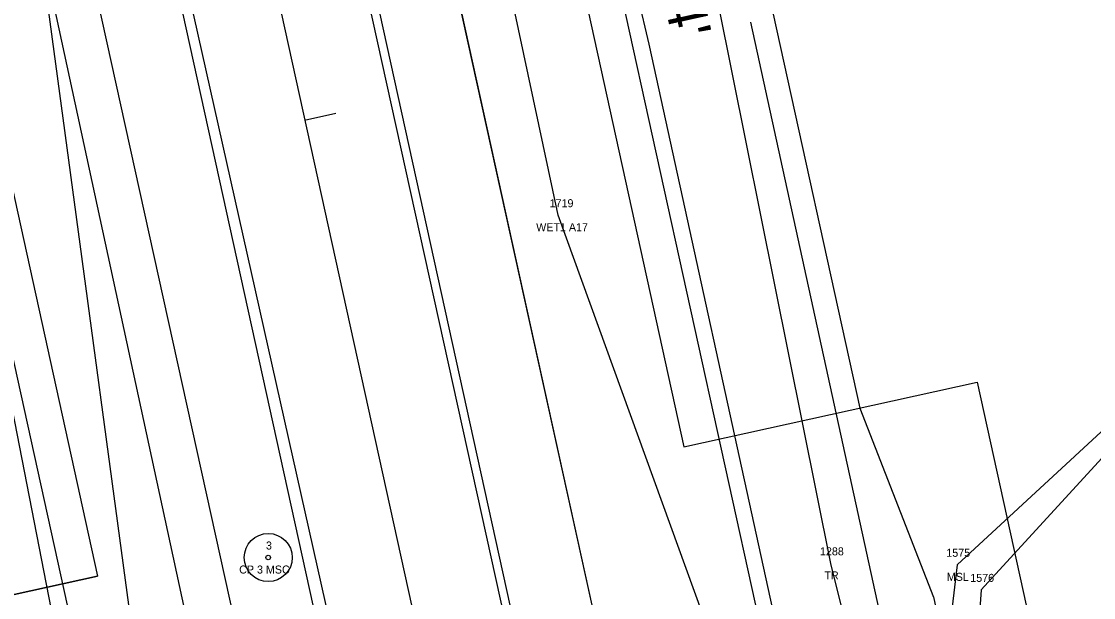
# Model space of a CAD drawing. Extents: x 2520975 to 2526538, y 881018 to 888064.
# Drawn here: x 2523710.8 to 2523844.7, y 885257.8 to 885329.7 of the extents above; entities that cross this region are included whole.
import ezdxf

# ---------------------------------------------------------------- set-up
doc = ezdxf.new("R2010")
doc.units = 0
for name, color, linetype in [('RD_EV_JurisArea', 7, 'Continuous'), ('RD_EX_DV_Prop', 7, 'Continuous'), ('RD_EX_H2O', 7, 'Continuous'), ('RD_EX_H2O_txCode', 7, 'Continuous'), ('RD_EX_H2O_WetLd_txCode', 7, 'Continuous'), ('RD_EX_Misc', 7, 'Continuous'), ('RD_EX_Misc_txCode', 7, 'Continuous'), ('RD_EX_Road', 7, 'Continuous'), ('RD_EX_RW', 7, 'Continuous'), ('RD_EX_VEG', 7, 'Continuous'), ('RD_EX_VEG_txCode', 7, 'Continuous'), ('RD_HC_Cl', 7, 'Continuous'), ('RD_HC_Data', 7, 'Continuous'), ('RD_HC_Data_Tic', 7, 'Continuous'), ('RD_HC_txCode', 7, 'Continuous'), ('RD_PD_BCA', 7, 'Continuous'), ('RD_PD_CstnLmt', 7, 'Continuous'), ('RD_PD_DR_ErosCtrl', 7, 'Continuous'), ('RD_PD_Final_TrvlWay', 7, 'Continuous'), ('RD_PD_GR', 7, 'Continuous'), ('RD_PD_RW', 7, 'Continuous'), ('RD_SMD_Locator', 7, 'Continuous')]:
    doc.layers.add(name, color=color, linetype=linetype)

msp = doc.modelspace()

# ---------------------------------------------------------------- linework, layer by layer
at = {"layer": 'RD_EV_JurisArea'}
for points in [[(2523761.17, 885134.03), (2523740.58, 885149.03), (2523730.55, 885209.77), (2523710.6, 885357.47), (2523698.09, 885411.19), (2523674.93, 885498.62), (2523657.6, 885564.24), (2523640.82, 885610.87), (2523583.66, 885726.91), (2523539.21, 885693.17), (2523494.42, 885646.98)], [(2523761.17, 885134.03), (2523808.21, 885149.21), (2523821.91, 885178.64), (2523802.85, 885236.55), (2523777.81, 885305.56), (2523748.2, 885444.32), (2523730.68, 885516.88), (2523708.64, 885617.3), (2523698.71, 885662.02), (2523727.83, 885665.82), (2523757.3, 885671.75)]]:
    msp.add_lwpolyline(points, dxfattribs=at)
at = {"layer": 'RD_EX_DV_Prop'}
for p, q in [((2523677.79, 885802.27), (2523793.53, 885276.66)), ((2523670.71, 885485.63), (2523720.28, 885260.53)), ((2523793.53, 885276.66), (2523830.15, 885284.72)), ((2523830.15, 885284.72), (2523894.67, 884991.74)), ((2523720.28, 885260.53), (2523683.66, 885252.46))]:
    msp.add_line(p, q, dxfattribs=at)
at = {"layer": 'RD_EX_H2O'}
msp.add_lwpolyline([(2524064.86, 885165.15), (2524036.37, 885213.78), (2524057.22, 885252.72), (2524031.95, 885291.63), (2523983.25, 885326.3), (2523940.61, 885311.83), (2523904.84, 885305.01), (2523874.98, 885272.1), (2523850.32, 885280.24), (2523830.66, 885258.8), (2523826.93, 885206.61)], dxfattribs=at)
at = {"layer": 'RD_EX_Misc'}
msp.add_lwpolyline([(2524066.31, 885165.35), (2524037.3, 885214.15), (2524057.95, 885253.07), (2524039.52, 885283.17), (2524032.92, 885292.57), (2523983.53, 885327.98), (2523940.24, 885313.27), (2523904.13, 885306.25), (2523874.86, 885272.67), (2523849.96, 885282.51), (2523827.65, 885261.93), (2523821.38, 885209.28)], dxfattribs=at)
at = {"layer": 'RD_EX_Road'}
for p, q in [((2523771.24, 885254.79), (2523751.35, 885344.92)), ((2523750.32, 885250.18), (2523730.02, 885340.63))]:
    msp.add_line(p, q, dxfattribs=at)
at = {"layer": 'RD_EX_RW'}
for p, q in [((2523677.79, 885802.27), (2523793.53, 885276.65)), ((2523670.71, 885485.63), (2523720.28, 885260.53)), ((2523793.53, 885276.65), (2523830.15, 885284.72)), ((2523830.15, 885284.72), (2523894.67, 884991.74)), ((2523683.66, 885252.46), (2523720.28, 885260.53))]:
    msp.add_line(p, q, dxfattribs=at)
at = {"layer": 'RD_EX_VEG'}
for points in [[(2523825.62, 885207.01), (2523811.87, 885262.11), (2523733.02, 885654.22), (2523687.11, 885876.24)], [(2523749.81, 885158.06), (2523732.86, 885248.57), (2523691.62, 885438.95), (2523639.52, 885601.04)]]:
    msp.add_lwpolyline(points, dxfattribs=at)
at = {"layer": 'RD_HC_Cl'}
for p, q in [((2523662.65, 885798.93), (2524219.24, 883271.29)), ((2523641.17, 885794.2), (2524197.76, 883266.56))]:
    msp.add_line(p, q, dxfattribs=at)
at = {"layer": 'RD_HC_Data'}
for radius in [3, 0.282]:
    msp.add_circle((2523741.6, 885262.84), radius, dxfattribs=at)
at = {"layer": 'RD_HC_Data_Tic'}
msp.add_line((2523746.15, 885317.42), (2523750.06, 885318.28), dxfattribs=at)
at = {"layer": 'RD_PD_BCA'}
for p, q in [((2523815.5, 885281.49), (2523824.71, 885257.89)), ((2523824.7, 885257.92), (2523830.05, 885233.47))]:
    msp.add_line(p, q, dxfattribs=at)
at = {"layer": 'RD_PD_CstnLmt'}
for p, q in [((2523766.59, 885424.32), (2523789.14, 885326.89)), ((2523789.14, 885326.89), (2523810.51, 885229.2)), ((2523704.35, 885308.21), (2523723.51, 885210.04))]:
    msp.add_line(p, q, dxfattribs=at)
at = {"layer": 'RD_PD_DR_ErosCtrl'}
msp.add_line((2523801.84, 885329.66), (2523823.21, 885231.97), dxfattribs=at)
at = {"layer": 'RD_PD_Final_TrvlWay'}
for p, q in [((2523712.87, 885663.87), (2524066.74, 884056.87)), ((2523636.68, 885619.27), (2523984.7, 884038.8)), ((2523720.24, 885490.91), (2524037.44, 884050.42)), ((2523696.8, 885485.75), (2524014, 884045.26))]:
    msp.add_line(p, q, dxfattribs=at)
at = {"layer": 'RD_PD_GR'}
for p, q in [((2523742.1, 885438.13), (2523790.49, 885218.39)), ((2523747.52, 885208.93), (2523699.13, 885428.66))]:
    msp.add_line(p, q, dxfattribs=at)
at = {"layer": 'RD_PD_RW'}
msp.add_line((2523767.12, 885501.23), (2523815.5, 885281.49), dxfattribs=at)
at = {"layer": 'RD_SMD_Locator'}
for centre in [(2523777.81, 885305.56), (2523741.6, 885262.84), (2523811.87, 885262.11), (2523827.65, 885261.93), (2523830.66, 885258.8)]:
    msp.add_circle(centre, 0.001, dxfattribs=at)

# ---------------------------------------------------------------- texts
at = {"layer": 'RD_EX_H2O_txCode'}
msp.add_text('1576', height=1, dxfattribs=at).set_placement((2523829.29, 885259.8))
at = {"layer": 'RD_EX_H2O_WetLd_txCode'}
for s, p in [('1719', (2523776.75, 885306.56)), ('WET1 A17', (2523775.07, 885303.56))]:
    msp.add_text(s, height=1, dxfattribs=at).set_placement(p)
at = {"layer": 'RD_EX_Misc_txCode'}
for s, p in [('1575', (2523826.3, 885262.93)), ('MSL', (2523826.36, 885259.93))]:
    msp.add_text(s, height=1, dxfattribs=at).set_placement(p)
at = {"layer": 'RD_EX_VEG_txCode'}
for s, p in [('1288', (2523810.52, 885263.11)), ('TR', (2523811.07, 885260.11))]:
    msp.add_text(s, height=1, dxfattribs=at).set_placement(p)
at = {"layer": 'RD_HC_txCode'}
for s, p in [('3', (2523741.32, 885263.84)), ('CP 3 MSC', (2523737.97, 885260.84))]:
    msp.add_text(s, height=1, dxfattribs=at).set_placement(p)
at = {"layer": 'RD_PD_CstnLmt'}
msp.add_text("F 44'", height=5, rotation=282.4185, dxfattribs=at).set_placement((2523788.96, 885341.63))

doc.saveas('drawing.dxf')
